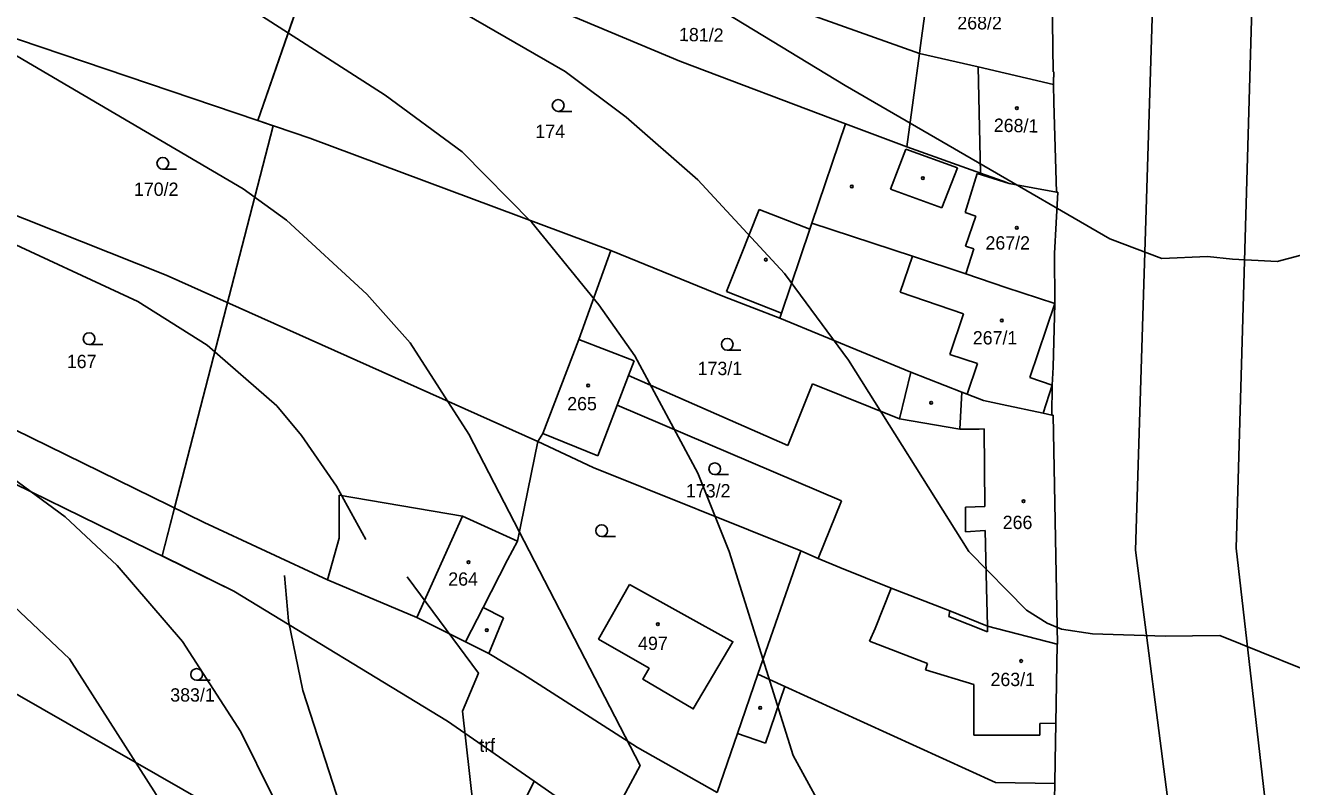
# Model space of a CAD drawing. Extents: x -555860 to -552701, y -1187050 to -1182291.
# Drawn here: x -554759.3 to -554597.5, y -1185002.9 to -1184905.7 of the extents above; entities that cross this region are included whole.
import ezdxf

# ---------------------------------------------------------------- set-up
doc = ezdxf.new("R2010")
doc.units = 0
for name, color, linetype in [('CYKLISTI_stav', 7, 'Continuous'), ('LEG_2b', 7, 'Continuous'), ('Level 16', 7, 'Continuous'), ('Level 25', 7, 'Continuous'), ('Level 32', 7, 'Continuous'), ('Level 40', 7, 'Continuous'), ('Level 41', 7, 'Continuous'), ('navrh_BV', 7, 'Continuous'), ('Poz předměty', 7, 'Continuous')]:
    doc.layers.add(name, color=color, linetype=linetype)

msp = doc.modelspace()

# ---------------------------------------------------------------- linework, layer by layer
at = {"layer": 'CYKLISTI_stav'}
for p, q in [((-554637.55, -1184910.99), (-554637.25, -1184924.57)), ((-554648.75, -1184926.59), (-554646.78, -1184921.5)), ((-554646.78, -1184921.5), (-554640.18, -1184923.87)), ((-554640.18, -1184923.87), (-554642.17, -1184928.97)), ((-554639.18, -1184929.56), (-554637.66, -1184924.6)), ((-554637.66, -1184924.6), (-554633.58, -1184925.88)), ((-554642.17, -1184928.97), (-554648.75, -1184926.59)), ((-554637.82, -1184930.03), (-554639.18, -1184929.56)), ((-554639.15, -1184933.88), (-554637.82, -1184930.03)), ((-554662.68, -1184942.42), (-554659.06, -1184931.73)), ((-554638.09, -1184934.22), (-554639.15, -1184933.88)), ((-554639.12, -1184937.43), (-554638.09, -1184934.22)), ((-554647.49, -1184939.77), (-554645.94, -1184935.14)), ((-554639.42, -1184942.53), (-554647.49, -1184939.77)), ((-554630.92, -1184950.65), (-554627.75, -1184941.22)), ((-554641.15, -1184947.7), (-554639.42, -1184942.53)), ((-554637.64, -1184948.84), (-554641.15, -1184947.7)), ((-554638.94, -1184952.76), (-554637.64, -1184948.84)), ((-554628.09, -1184951.61), (-554630.92, -1184950.65)), ((-554629.25, -1184955.2), (-554628.09, -1184951.61)), ((-554639.86, -1184957.26), (-554639.63, -1184952.5)), ((-554647.6, -1184955.91), (-554639.86, -1184957.26)), ((-554639.86, -1184957.26), (-554639.29, -1184957.25)), ((-554639.29, -1184957.25), (-554637.4, -1184957.23)), ((-554637.4, -1184957.23), (-554636.78, -1184957.22)), ((-554636.78, -1184957.22), (-554636.7, -1184967.11)), ((-554639.15, -1184967.19), (-554639.17, -1184970.34)), ((-554636.7, -1184967.11), (-554639.15, -1184967.19)), ((-554703.45, -1184968.37), (-554709.26, -1184981.28)), ((-554639.17, -1184970.34), (-554636.66, -1184970.17)), ((-554636.66, -1184970.17), (-554636.48, -1184977.49)), ((-554650.7, -1184982.7), (-554648.66, -1184977.56)), ((-554636.48, -1184977.49), (-554636.36, -1184982.42)), ((-554703.04, -1184984.4), (-554700.79, -1184980.02)), ((-554641.16, -1184980.45), (-554641.29, -1184981.15)), ((-554641.29, -1184981.15), (-554636.34, -1184983.13)), ((-554651.44, -1184984.3), (-554650.7, -1184982.7)), ((-554636.34, -1184983.13), (-554636.36, -1184982.42)), ((-554644.03, -1184987.17), (-554651.44, -1184984.3)), ((-554644.27, -1184987.96), (-554644.03, -1184987.17)), ((-554638.09, -1184989.86), (-554644.27, -1184987.96)), ((-554664.72, -1184997.33), (-554662.23, -1184990.11)), ((-554638.08, -1184996.33), (-554638.09, -1184989.86)), ((-554627.63, -1184994.79), (-554629.65, -1184994.83)), ((-554629.65, -1184994.83), (-554629.64, -1184996.31)), ((-554668.31, -1184996.1), (-554664.72, -1184997.33)), ((-554629.64, -1184996.31), (-554638.08, -1184996.33))]:
    msp.add_line(p, q, dxfattribs=at)
msp.add_lwpolyline([(-554682.08, -1184977.07), (-554668.88, -1184984.38), (-554673.95, -1184992.97), (-554680.39, -1184989.17), (-554679.59, -1184987.78), (-554686.04, -1184984.04), (-554682.08, -1184977.07)], dxfattribs=at)
at = {"layer": 'Level 25'}
for p, q in [((-554691.21, -1184916.67), (-554689.46, -1184916.67)), ((-554741.74, -1184924.05), (-554739.99, -1184924.05)), ((-554751.16, -1184946.45), (-554749.41, -1184946.45)), ((-554669.61, -1184947.16), (-554667.86, -1184947.16)), ((-554671.2, -1184963.05), (-554669.45, -1184963.05)), ((-554685.65, -1184970.96), (-554683.9, -1184970.96)), ((-554737.42, -1184989.31), (-554735.67, -1184989.31))]:
    msp.add_line(p, q, dxfattribs=at)
for centre, radius in [((-554691.21, -1184915.92), 0.75), ((-554632.58, -1184916.26), 0.175), ((-554741.74, -1184923.3), 0.75), ((-554653.69, -1184926.26), 0.175), ((-554644.6, -1184925.19), 0.175), ((-554632.6, -1184931.53), 0.175), ((-554664.66, -1184935.6), 0.175), ((-554634.51, -1184943.37), 0.175), ((-554751.16, -1184945.7), 0.75), ((-554669.61, -1184946.41), 0.75), ((-554687.39, -1184951.66), 0.175), ((-554643.54, -1184953.87), 0.175), ((-554671.2, -1184962.3), 0.75), ((-554631.73, -1184966.45), 0.175), ((-554685.65, -1184970.21), 0.75), ((-554702.66, -1184974.24), 0.175), ((-554700.34, -1184982.9), 0.175), ((-554678.47, -1184982.14), 0.175), ((-554632.04, -1184986.85), 0.175), ((-554737.42, -1184988.56), 0.75), ((-554665.39, -1184992.84), 0.175)]:
    msp.add_circle(centre, radius, dxfattribs=at)
at = {"layer": 'Level 32'}
for points in [[(-554732.66, -1184977.91), (-554741.83, -1184973.43), (-554727.63, -1184918.52), (-554729.6, -1184917.85), (-554721.19, -1184893.59), (-554717.6, -1184874.5)], [(-554688.49, -1185135.67), (-554674.12, -1185087.36), (-554669.8, -1185074.16), (-554667.89, -1185069.33), (-554666.61, -1185061.26), (-554666.18, -1185059.07), (-554670.81, -1185057.05), (-554678.5, -1185053.7), (-554699.04, -1185044.99), (-554707.18, -1185041.55), (-554704.89, -1185035.88), (-554704.08, -1185033.86), (-554701.54, -1185027.57), (-554700.42, -1185024.78), (-554704.58, -1185023.01), (-554694.27, -1185002.2), (-554705.36, -1184994.55), (-554732.66, -1184977.91)]]:
    msp.add_lwpolyline(points, dxfattribs=at)
at = {"layer": 'Level 40'}
for points in [[(-554753.25, -1184888.97), (-554713.32, -1184914.62), (-554703.47, -1184921.83), (-554694.6, -1184930.84), (-554686, -1184941.38), (-554681.42, -1184947.9), (-554673.38, -1184962.87), (-554669.36, -1184972.85), (-554661.18, -1184998.92), (-554651.22, -1185017.13), (-554653.36, -1185021.96), (-554653, -1185023.74), (-554646.9, -1185029.84), (-554639.96, -1185035.39), (-554629.94, -1185038.24), (-554619.55, -1185039.95), (-554616.33, -1185032.7), (-554610.02, -1185014.45), (-554603.18, -1185013.37), (-554600.22, -1185015.78), (-554589.63, -1185026.24)], [(-554763.23, -1184977.57), (-554753.66, -1184986.58), (-554742.57, -1185003.91), (-554727.6, -1185035.53), (-554723.83, -1185045.91), (-554720.39, -1185056.6), (-554716.07, -1185072.64), (-554713.87, -1185082.95), (-554709.29, -1185109.29), (-554701.71, -1185171.5), (-554701.71, -1185175.79)]]:
    msp.add_lwpolyline(points, dxfattribs=at)
at = {"layer": 'Level 41'}
for points in [[(-554694.46, -1184889.1), (-554654.53, -1184913.37), (-554620.71, -1184932.96), (-554614.05, -1184935.45), (-554608.22, -1184935.19), (-554605.05, -1184935.56), (-554599.34, -1184935.83), (-554593.52, -1184934.31), (-554588.92, -1184931.8), (-554584.09, -1184928.62), (-554577.57, -1184923.21), (-554561.62, -1184903.94)], [(-554723.3, -1184892.57), (-554690.3, -1184911.57), (-554682.53, -1184917.39), (-554673.38, -1184925.43), (-554662.29, -1184937.36), (-554654.11, -1184948.45), (-554638.72, -1184972.85), (-554631.37, -1184980.34), (-554628.73, -1184982), (-554626.87, -1184982.79), (-554622.91, -1184983.39), (-554613.64, -1184983.67), (-554606.66, -1184983.57), (-554591.02, -1184989.91)], [(-554663.04, -1185054.31), (-554670.19, -1185043.29), (-554674.21, -1185033.59), (-554682.89, -1185004.24), (-554680.74, -1185000.21), (-554702.64, -1184957.88), (-554710.13, -1184946.23), (-554715.67, -1184939.99), (-554725.93, -1184930.56), (-554731.48, -1184926.54), (-554778.76, -1184898.81), (-554787.08, -1184895.48), (-554790.96, -1184895.48), (-554794.85, -1184896.73), (-554798.04, -1184898.53), (-554806.77, -1184906.99), (-554822.85, -1184920.86), (-554828.4, -1184924.46), (-554842.41, -1184931.53)], [(-554815.82, -1184932), (-554812.59, -1184930.43), (-554807.88, -1184926.96), (-554799.56, -1184919.05), (-554796.1, -1184916.46), (-554792.21, -1184914.2), (-554790.33, -1184913.49), (-554787.91, -1184913.51), (-554785.38, -1184915.14), (-554777.95, -1184922.89), (-554771, -1184928.07), (-554763.51, -1184932.36), (-554744.93, -1184940.96), (-554736.06, -1184946.51), (-554727.18, -1184954.27), (-554724.03, -1184958.04), (-554719.56, -1184964.53), (-554715.81, -1184971.33)], [(-554763.93, -1184961.34), (-554754.22, -1184968.42), (-554747.56, -1184974.66), (-554739.24, -1184984.36), (-554731.76, -1184995.87), (-554727.73, -1185004.05), (-554718.86, -1185028.04), (-554709.16, -1185051.33), (-554705.97, -1185062.98), (-554704.03, -1185072.31), (-554702.36, -1185084.33), (-554697.65, -1185125.1), (-554692.82, -1185154.47)], [(-554683.62, -1185124.45), (-554690.3, -1185083.78), (-554692.52, -1185072.69), (-554699.31, -1185052.72), (-554719.56, -1185003.91), (-554723.85, -1184990.6), (-554725.66, -1184981.73), (-554726.17, -1184975.93)], [(-554710.51, -1184976.11), (-554701.4, -1184988.4), (-554703.43, -1184993.27), (-554700.7, -1185017.5), (-554690.71, -1185042.74), (-554684.61, -1185056.32), (-554672.83, -1185090.69)]]:
    msp.add_lwpolyline(points, dxfattribs=at)
at = {"layer": 'navrh_BV'}
for p, q in [((-554617.44, -1184972.71), (-554612.53, -1184818.21)), ((-554604.58, -1184972.42), (-554600.09, -1184818.4)), ((-554645.03, -1184909.26), (-554702.72, -1184888.74)), ((-554721.19, -1184893.59), (-554729.6, -1184917.85)), ((-554787.72, -1184898.17), (-554729.6, -1184917.85)), ((-554675.68, -1184910.27), (-554702.93, -1184898.82)), ((-554628.13, -1184899.67), (-554627.94, -1184911.61)), ((-554644.93, -1184908.55), (-554643.92, -1184901.17)), ((-554645.03, -1184909.26), (-554646.67, -1184921.21)), ((-554644.93, -1184908.55), (-554645.03, -1184909.26)), ((-554637.55, -1184910.99), (-554645.03, -1184909.26)), ((-554654.51, -1184918.26), (-554675.68, -1184910.27)), ((-554627.91, -1184913.22), (-554637.55, -1184910.99)), ((-554627.94, -1184911.61), (-554627.86, -1184911.61)), ((-554627.86, -1184911.61), (-554627.88, -1184912.31)), ((-554627.91, -1184913.22), (-554627.93, -1184912.31)), ((-554627.88, -1184912.31), (-554627.93, -1184912.31)), ((-554627.85, -1184915.54), (-554627.91, -1184913.22)), ((-554627.85, -1184915.54), (-554627.54, -1184927)), ((-554729.6, -1184917.85), (-554722.97, -1184920.1)), ((-554741.31, -1184937.6), (-554789.59, -1184918.36)), ((-554654.51, -1184918.26), (-554658.79, -1184930.93)), ((-554646.67, -1184921.21), (-554654.51, -1184918.26)), ((-554722.97, -1184920.1), (-554684.47, -1184934.43)), ((-554637.25, -1184924.57), (-554646.67, -1184921.21)), ((-554634.36, -1184925.6), (-554637.25, -1184924.57)), ((-554633.58, -1184925.88), (-554634.36, -1184925.6)), ((-554627.54, -1184927), (-554633.58, -1184925.88)), ((-554627.76, -1184934.8), (-554627.37, -1184926.99)), ((-554627.37, -1184926.99), (-554627.54, -1184927)), ((-554665.54, -1184929.18), (-554667.93, -1184935.22)), ((-554659.06, -1184931.73), (-554665.54, -1184929.18)), ((-554658.79, -1184930.93), (-554659.06, -1184931.73)), ((-554658.79, -1184930.93), (-554645.94, -1184935.14)), ((-554688.56, -1184945.8), (-554684.47, -1184934.43)), ((-554684.47, -1184934.43), (-554669.96, -1184940.33)), ((-554667.93, -1184935.22), (-554669.7, -1184939.68)), ((-554645.94, -1184935.14), (-554639.12, -1184937.43)), ((-554627.75, -1184941.22), (-554627.76, -1184934.8)), ((-554639.12, -1184937.43), (-554634.02, -1184939.14)), ((-554693.83, -1184958.8), (-554741.31, -1184937.6)), ((-554634.02, -1184939.14), (-554627.75, -1184941.22)), ((-554669.96, -1184940.33), (-554662.9, -1184943.08)), ((-554669.7, -1184939.68), (-554662.68, -1184942.42)), ((-554627.97, -1184949.31), (-554627.75, -1184941.22)), ((-554662.68, -1184942.42), (-554662.9, -1184943.08)), ((-554662.9, -1184943.08), (-554646.15, -1184949.97)), ((-554783.8, -1184945.99), (-554736.45, -1184969.17)), ((-554693.17, -1184957.8), (-554688.56, -1184945.8)), ((-554688.56, -1184945.8), (-554681.49, -1184948.52)), ((-554681.49, -1184948.52), (-554682.22, -1184950.41)), ((-554682.22, -1184950.41), (-554683.67, -1184954.19)), ((-554682.22, -1184950.41), (-554661.88, -1184959.33)), ((-554647.6, -1184955.91), (-554646.15, -1184949.97)), ((-554646.15, -1184949.97), (-554639.63, -1184952.5)), ((-554628.09, -1184951.61), (-554627.97, -1184949.31)), ((-554661.88, -1184959.33), (-554658.73, -1184951.45)), ((-554658.73, -1184951.45), (-554647.6, -1184955.91)), ((-554628.14, -1184955.46), (-554628.09, -1184951.61)), ((-554639.63, -1184952.5), (-554638.94, -1184952.76)), ((-554638.94, -1184952.76), (-554636.84, -1184953.57)), ((-554636.84, -1184953.57), (-554634.49, -1184954.08)), ((-554732.66, -1184977.91), (-554781.86, -1184953.89)), ((-554683.67, -1184954.19), (-554686.16, -1184960.67)), ((-554683.67, -1184954.19), (-554655.02, -1184966.38)), ((-554634.49, -1184954.08), (-554629.25, -1184955.2)), ((-554629.25, -1184955.2), (-554628.14, -1184955.46)), ((-554628.14, -1184955.46), (-554627.97, -1184955.47)), ((-554627.97, -1184955.47), (-554627.4, -1184984.69)), ((-554693.83, -1184958.8), (-554693.17, -1184957.8)), ((-554686.16, -1184960.67), (-554693.17, -1184957.8)), ((-554696.43, -1184971.53), (-554693.83, -1184958.8)), ((-554686.72, -1184962.13), (-554693.83, -1184958.8)), ((-554660.2, -1184972.77), (-554686.72, -1184962.13)), ((-554719.22, -1184971.16), (-554719.2, -1184965.67)), ((-554719.2, -1184965.67), (-554703.45, -1184968.37)), ((-554655.02, -1184966.38), (-554657.99, -1184973.78)), ((-554736.45, -1184969.17), (-554720.7, -1184976.47)), ((-554703.45, -1184968.37), (-554696.43, -1184971.53)), ((-554720.7, -1184976.47), (-554719.22, -1184971.16)), ((-554696.43, -1184971.53), (-554697.67, -1184973.95)), ((-554665.71, -1184988.52), (-554660.2, -1184972.77)), ((-554657.99, -1184973.78), (-554660.2, -1184972.77)), ((-554612.64, -1185009.67), (-554617.44, -1184972.71)), ((-554596.47, -1185043.12), (-554604.58, -1184972.42)), ((-554789.28, -1184974.63), (-554704.58, -1185023.01)), ((-554697.67, -1184973.95), (-554700.79, -1184980.02)), ((-554655.21, -1184974.91), (-554657.99, -1184973.78)), ((-554648.66, -1184977.56), (-554655.21, -1184974.91)), ((-554705.36, -1184994.55), (-554732.66, -1184977.91)), ((-554709.26, -1184981.28), (-554720.7, -1184976.47)), ((-554641.16, -1184980.45), (-554648.66, -1184977.56)), ((-554700.79, -1184980.02), (-554698.19, -1184981.35)), ((-554636.36, -1184982.42), (-554641.16, -1184980.45)), ((-554703.04, -1184984.4), (-554709.26, -1184981.28)), ((-554698.19, -1184981.35), (-554700.07, -1184985.89)), ((-554627.45, -1184984.69), (-554636.36, -1184982.42)), ((-554700.07, -1184985.89), (-554703.04, -1184984.4)), ((-554695.77, -1184988.49), (-554700.07, -1184985.89)), ((-554627.45, -1184984.69), (-554627.63, -1184994.79)), ((-554627.4, -1184984.69), (-554627.45, -1184984.69)), ((-554681.09, -1184997.91), (-554695.77, -1184988.49)), ((-554668.31, -1184996.1), (-554665.71, -1184988.52)), ((-554665.71, -1184988.52), (-554662.23, -1184990.11)), ((-554662.23, -1184990.11), (-554635.34, -1185002.37)), ((-554694.27, -1185002.2), (-554705.36, -1184994.55)), ((-554627.63, -1184994.79), (-554627.71, -1184999.62)), ((-554670.9, -1185003.65), (-554668.31, -1184996.1)), ((-554670.9, -1185003.65), (-554681.09, -1184997.91)), ((-554627.71, -1184999.62), (-554627.75, -1185002.49)), ((-554689.75, -1185005.32), (-554694.27, -1185002.2)), ((-554635.34, -1185002.37), (-554627.75, -1185002.49)), ((-554627.75, -1185002.49), (-554627.84, -1185007.58))]:
    msp.add_line(p, q, dxfattribs=at)
at = {"layer": 'Poz předměty'}
msp.add_lwpolyline([(-554741.83, -1184973.43), (-554740.25, -1184967.31), (-554727.63, -1184918.52)], dxfattribs=at)

# ---------------------------------------------------------------- texts
at = {"layer": 'LEG_2b'}
for s, p in [('268/2', (-554640.2, -1184906.2)), ('174', (-554694.13, -1184920.07)), ('170/2', (-554745.43, -1184927.46)), ('267/2', (-554636.6, -1184934.31)), ('267/1', (-554638.22, -1184946.43)), ('167', (-554754.01, -1184949.45)), ('173/1', (-554673.39, -1184950.34)), ('265', (-554690.06, -1184954.84)), ('173/2', (-554674.88, -1184965.96)), ('266', (-554634.4, -1184970)), ('264', (-554705.26, -1184977.23)), ('497', (-554681, -1184985.44)), ('263/1', (-554635.96, -1184990.05)), ('383/1', (-554740.79, -1184992.03))]:
    msp.add_text(s, height=1.7, dxfattribs=at).set_placement(p)
for s, p in [('181/2', (-554675.78, -1184907.69)), ('268/1', (-554635.55, -1184919.28))]:
    msp.add_text(s, height=1.7, rotation=359, dxfattribs=at).set_placement(p)
at = {"layer": 'Level 16'}
msp.add_text('trf', height=1.7, dxfattribs=at).set_placement((-554701.29, -1184998.45))

doc.saveas('drawing.dxf')
